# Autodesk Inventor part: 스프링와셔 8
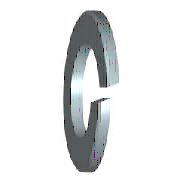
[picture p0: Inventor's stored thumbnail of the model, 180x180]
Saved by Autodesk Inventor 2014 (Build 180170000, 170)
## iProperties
IsCustomPart: 1
Created: 2012-02
Part Number: 스프링와셔 8
Material: 강철, 연강
Description: 스프링 잠금 와셔
Document SubType Name: Modeling
Standard: KS B 1324
Designer: mduedu
Standards Organization: KS
Language: ko-KR
Size Designation: 번호 3 - 8
Categories: <MemberInstance><Categories><Category DisplayName="조임쇠" InternalName="e4da775c-781d-43d5-af7c-5136215cf5a6" Mnemonic="FSTN"><Category DisplayName="와셔" InternalN
Density: 7.86 g/cm^3
Mass: 2.2775 g
Surface Area: 4.25113 cm^2
Volume: 0.289759 cm^3
Appearance: 파란색 - 벽 페인트 - 광택
Author: mduedu
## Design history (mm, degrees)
sketch "스케치1"
  geometry: C1 r 7.4 at (0, 0); C2 r 4.1 at (0, 0); 1 further point
  constraints: 2 centre point, 2 coincident
  dimensions: "d0" = 8.2 diameter of C2 (= SD1); "d1" = 14.8 diameter of C1 (= SD2)
extrude "본체" new body sketch "스케치1" distance "d2" = 2.5 (= SD); taper "d3" = 0 deg
sketch "스케치2"
  geometry: L1 (0, -4.1)-(0, 4.1) reference; L2 (2.5, 7.4)-(2.5, -7.4) reference; L3 (-1.2, 0)-(7.2, 0) reference; L4 (0, -0.5)-(2.5, 0.41); L5 (0, 0.5)-(2.5, 1.41)
  constraints: 4 end point, 4 point on line, 1 parallel
  dimensions: "d4" = 0.5 distance from line of L3 L4.start (= 0.2 x SD); "d5" = 0.5 distance from line of L3 L5.start (= 0.2 x SD); "d6" = 70 deg angle of L2 L4 (= FAWI)
extrude "절단부" cut sketch "스케치2" stored distance "d7" = 2.5 (= SD); taper "d8" = 0 deg
workaxis "Work Axis1"
workplane "Work Plane1"
body "Solid1"
other parameters: "SD1" = 8.2 [user parameter; used in 1 equation term], "SD2" = 14.8 [user parameter; used in 1 equation term], "SD" = 2.5 [user parameter; used in 4 equation terms], "FAWI" = 70 deg [user parameter; used in 1 equation term], "d9" = 0, "d10" = 0, "d11" = 0, "d12" = 0, "SDI" = 3.3 [user parameter], "NND" = 8 [user parameter]
